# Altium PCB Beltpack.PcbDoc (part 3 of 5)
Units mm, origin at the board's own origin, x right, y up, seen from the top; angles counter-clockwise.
Board outline 85 x 81 mm, 4 copper layers (Top Layer, Inner-1, Inner_GND, Bottom Layer), stack 1.556 mm thick; 389 components, 291 nets, 1372 pads, 660 vias.
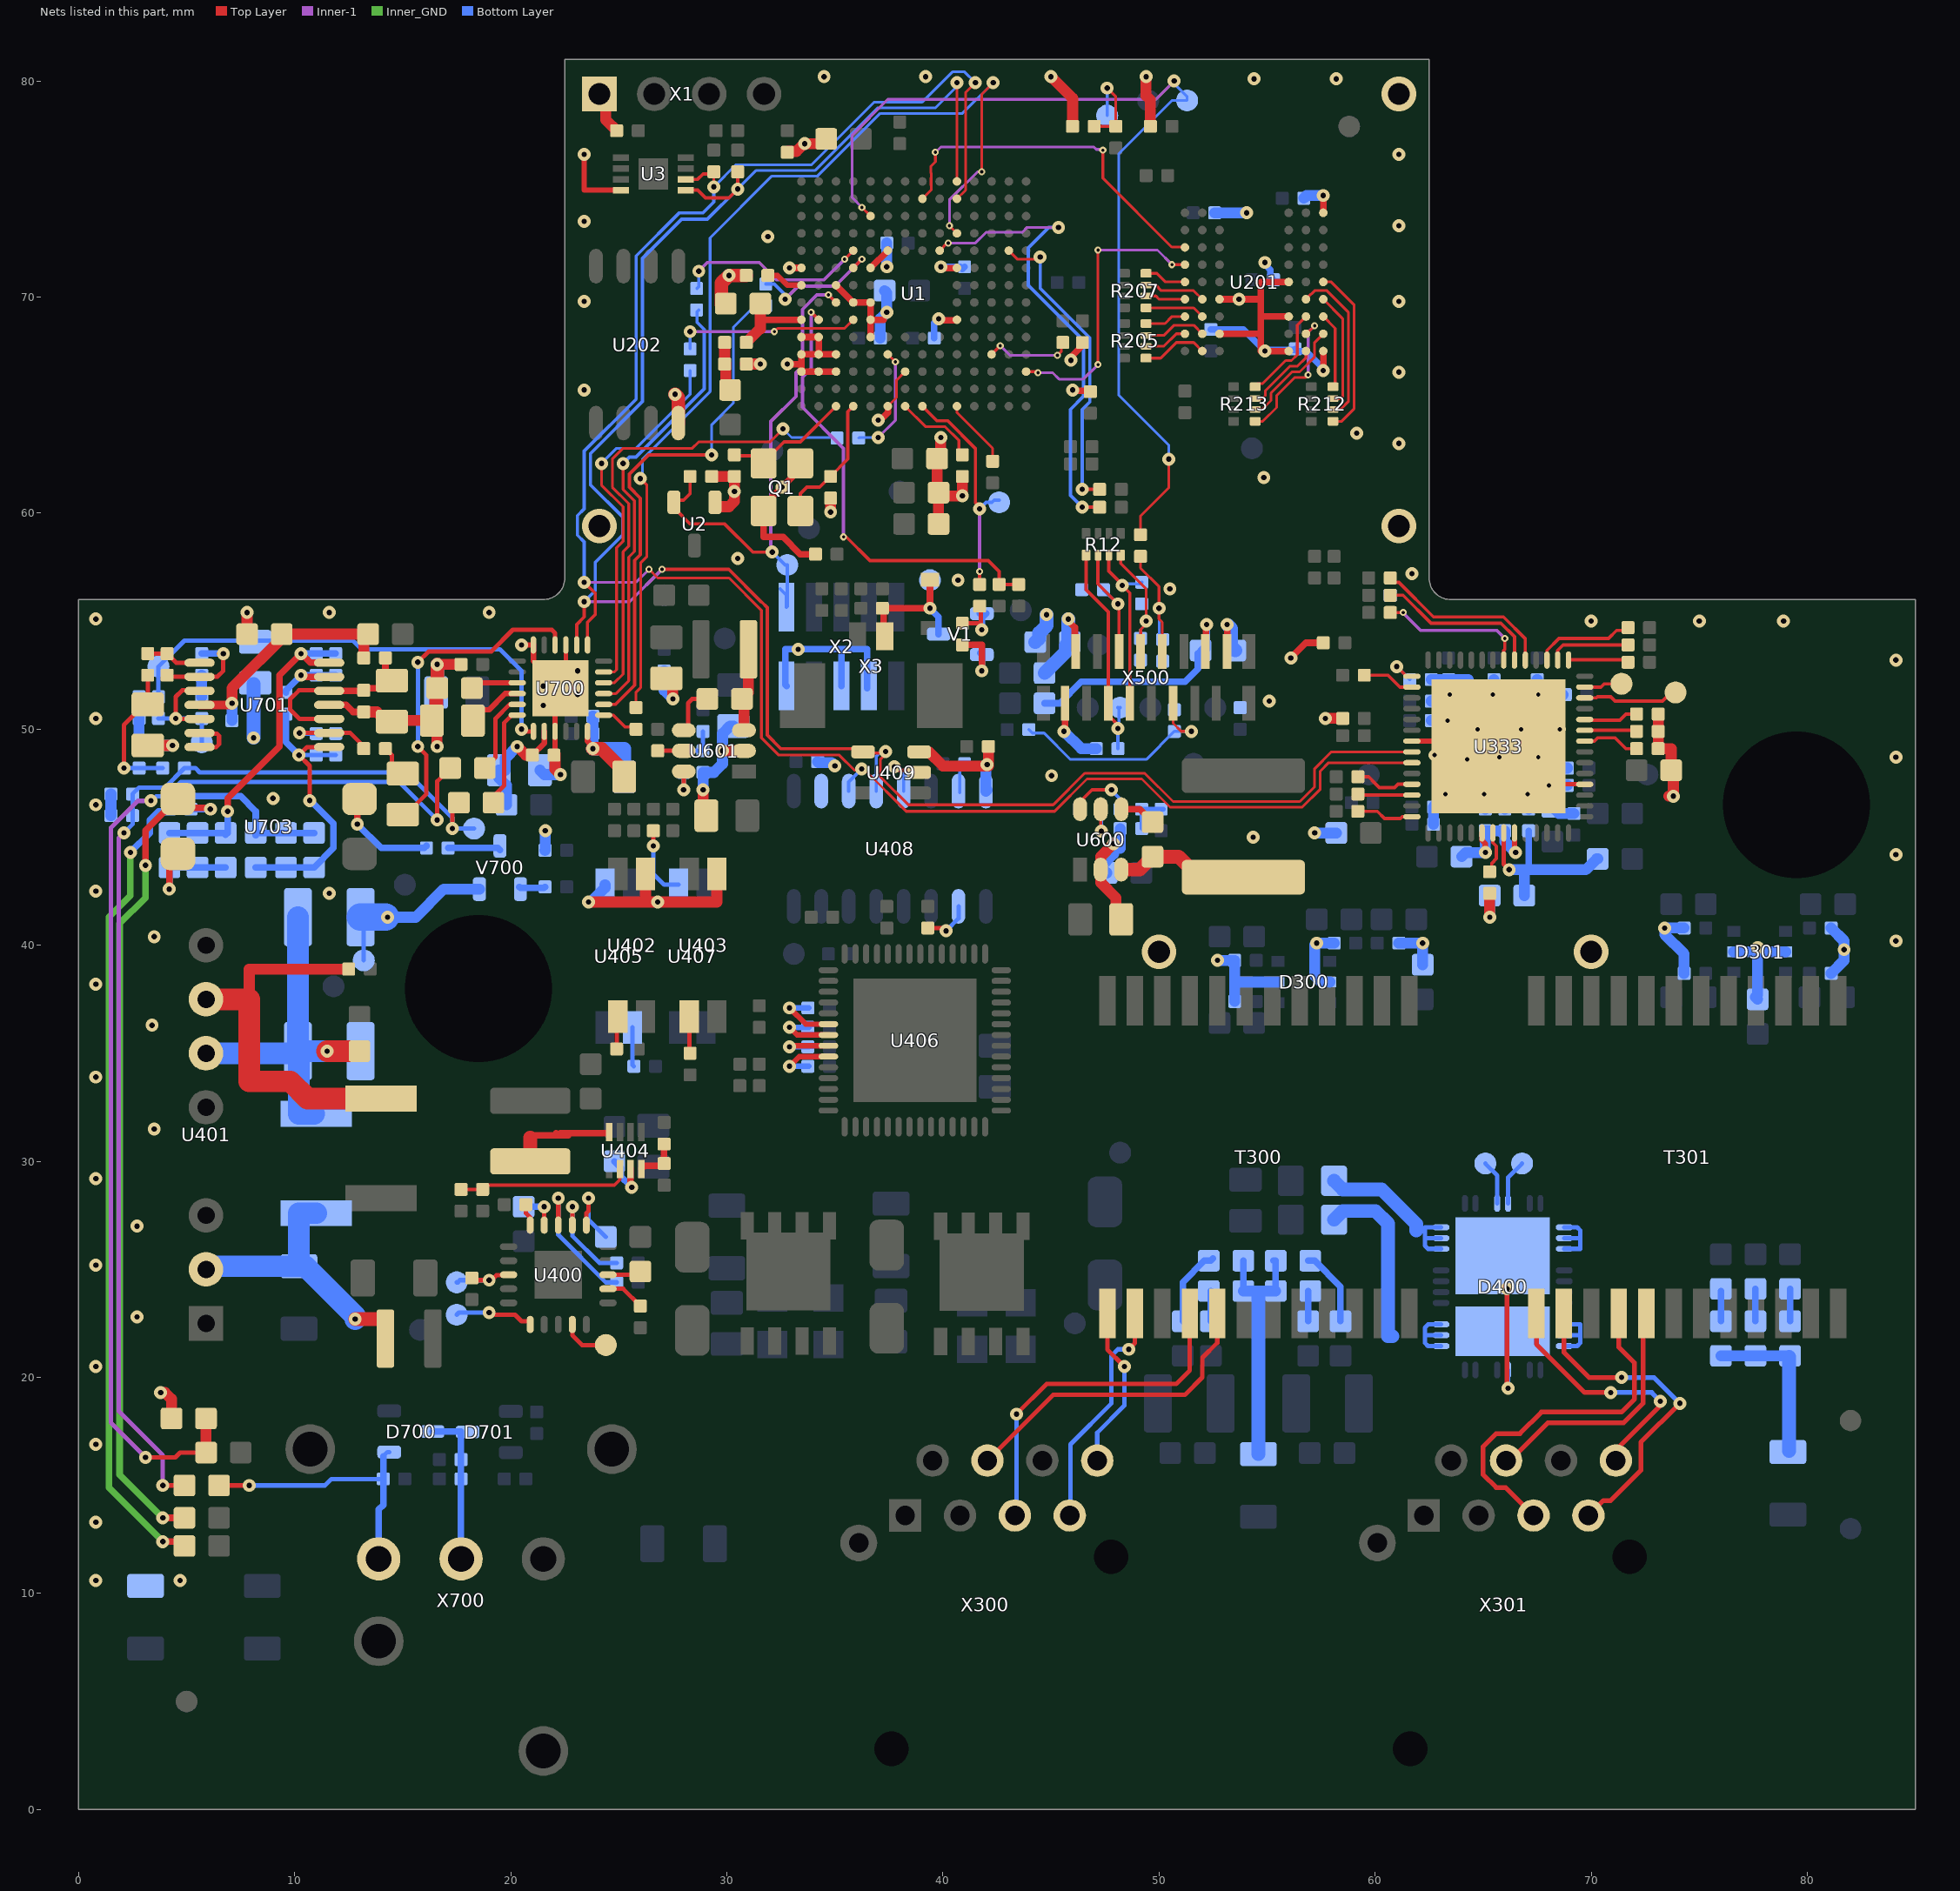
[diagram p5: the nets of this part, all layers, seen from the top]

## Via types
v1: diameter 0.6, hole 0.25, Top Layer to Bottom Layer, 460 vias
v2: diameter 0.325, hole 0.15, Top Layer to Inner-1, 145 vias
v3: diameter 0.55, hole 0.2, Top Layer to Bottom Layer, 41 vias
v4: diameter 0.325, hole 0.15, Top Layer to Inner-1, tented both sides, 8 vias
v5: diameter 1.6, hole 1.016, Top Layer to Bottom Layer, 5 vias
v6: diameter 0.6, hole 0.25, Top Layer to Bottom Layer, tented both sides, 1 vias

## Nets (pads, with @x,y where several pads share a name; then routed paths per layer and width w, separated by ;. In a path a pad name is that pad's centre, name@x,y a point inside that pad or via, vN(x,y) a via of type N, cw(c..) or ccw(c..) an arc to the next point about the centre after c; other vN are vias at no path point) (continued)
GND: C1.2 C2.2 C3.1 C5.1 C6.2 C7.2 C8.2 C9.2 C10.2 C11.2 C12.2 C13.2 C14.2 C15.2 C16.2 C17.1 C18.1 C19.1 C20.1 C21.1 C22.1 C23.1 C24.1 C200.2 C201.2 C202.2 C203.2 C204.2 C205.2 C206.1 C300.2 C301.2 C302.2 C303.2 C304.2 C305.2 C306.2 C307.2 C308.2 C309.2 C310.1 C311.2 C312.2 C313.2 C315.2 C316.2 C317.2 C318.2 C319.2 C320.2 C323.2 C328.2 C330.1 C332.1 C333.2 C334.2 C335.2 C336.2 C406.2 C408.2 C417.1 C418.2 C419.2 C601.2 C602.2 C604.2 C605.1 C606.1 C607.2 C700.1 C701.1 C702.1 C703.1 C704.1 C705.1 C706.1 C707.1 C708.1 C709.1 C713.1 C715.1 C716.2 C717.2 C722.1 C723.1 C724.1 C725.1 C726.1 D300.2 D300.5 D301.2 D301.5 Q1.2 Q1.4 R2.1 R3.2 R9.2 R11.2 R204.2 R208.2 R209.1 R210.2 R218.2 R300.1 R320.2 R321.1 R322.2 R325.1 R331.2 R337.1 R338.1 R603.2 R607.2 R705.2 R707.2 R712.1 R722.2 R723.2 R724.2 TP407.1 U1.A3 U1.A4 U1.A5 U1.A9 U1.B3 U1.B4 U1.B5 U1.C3 U1.C4 U1.C8 U1.D7 U1.E5 U1.E6 U1.E7 U1.E9 U1.F1 U1.F10 U1.G3 U1.K6 U1.K9 U2.1 U3.4 U201.A1 U201.A3 U201.B7 U201.C3 U201.D7 U201.E3 U201.J1 U202.4 U333.4 U333.35 U333.57 U401.7 U402.3 U403.3 U405.3 U408.2 U408.8 U409.3 U600.2 U601.2 U700.3 U700.6 U700.15 U700.18 U700.25 U701.11 V1.2 V700.2 X1.1 X2.3 X2.5 X2.9 X4.1 X5.1 X6.1 X7.1 X8.1 X500.1 X500.16 | length 254.9
  Top Layer w0.127: U1.F1@37.45,64.95 37.85,65.35 37.85,66.15 U1.G3@38.25,66.55
  Top Layer w0.203: U700.25@22.3,51.9 22.55,52.15 U700.15@22.55,53.9 ; U333.57@68,47.4 68.05,47.45 U333.4@69.7,47.45
  Top Layer w0.254: v1(20.5,53.9) U700.18@21.05,53.9 21.05,53.15 U700.25@22.3,51.9 22.05,51.65 U700.3@22.05,49.9 C704.1@22.05,48.85 ; v1(23.4,76.6) 23.4,74.95 U3.4@25.1,74.95 ; U700.6@23.55,49.9 23.55,49.45 23.8,49.2 v1(23.8,49.1) ; U333.35@61.7,49.45 U333.57@65.45,49.45
  Top Layer w0.305: U701.11@11.6,51.125 12.375,51.125 12.7,50.8 R722.2@13.2,50.8 ; Q1.2@31.575,60.225 v1(32.55,61.2) 33.4,62.05 Q1.4@33.4,62.3 ; Q1.2@31.7,60.1 31.7,58.9 32.6,58.9 33.4,58.1 34,58.1 R9.2@34.1,58.2 ; v6(32.9,71.35) U1.A9@33.45,71.35 ; v1@32.95,66.95 33,66.9 33.45,66.9 U1.A3@33.45,66.55 U1.B3@34.25,66.55 U1.C3@35.05,66.55 ; 33.45,66.95 U1.A4@33.45,67.35 U1.B4@34.25,67.35 ; U1.A5@33.45,68.15 U1.B5@34.25,68.15 ; U1.B5@34.25,68.1 U1.B4@34.25,67.35 ; U1.C4@34.95,67.35 U1.B4@34.25,67.35 ; U1.C8@35.05,70.55 U1.D7@35.85,69.75 U1.E7@36.65,69.75 U1.E6@36.65,68.95 ; U1.E5@36.65,68.15 U1.E6@36.65,68.95 ; U1.E9@36.65,71.35 U1.F10@37.45,72.15 U1.F10@37.45,72.2 ; v1(37,64.3) 37.056,64.356 37.156,64.356 37.45,64.65 U1.F1@37.45,64.95 ; 37.25,68.95 U1.E6@36.65,68.95 ; v1(39.8,69) 39.868,68.932 40.632,68.932 U1.K6@40.65,68.95 U1.K6@40.632,68.968 ; v1(39.9,71.4) 39.956,71.344 40.056,71.344 40.068,71.332 40.632,71.332 U1.K9@40.65,71.35 ; R11.2@40.9,53.9 41.8,53.9 v1(41.8,52.7) ; v1@45.65,49.95 X500.1@45.65,51.2 ; v1@45.975,67.125 45.975,67.275 46.45,67.75 46.45,67.894 C206.1@46.456,67.899 ; v1(46,65.7) 46.038,65.663 46.787,65.663 R204.2@46.825,65.625 ; U201.B7@52.8,68.3 54.7,68.3 ; U201.D7@52.8,69.9 54.7,69.9 ; X500.16@53.15,53.6 v1(53.15,54.85) ; U201.A3@56,67.5 54.7,67.5 54.7,68.3 ; U201.C3@56,69.1 54.7,69.1 ; U201.E3@56,70.7 54.7,70.7 54.7,69.9 ; v1(56.1,53.3) 56.8,54 R338.1@57.6,54 ; v1(57.6,66.6) U201.A1@57.6,67.5 ; U201.J1@57.6,73.9 v1(57.6,74.7) ; 54.7,68.3 54.7,69.1 ; 54.7,69.1 54.7,69.9
  Top Layer w0.508: C717.2@3.2,49.25 v1(4.35,49.25) ; v1(3.8,19.3) 4,19.3 4.3,19 R712.1@4.3,18.1 ; C722.1@7.7,54.3 C722.1@7.8,54.4 v1(7.8,55.4) ; 7.9,37.5 7.9,38.9 11.6,38.9 C418.2@12.5,38.9 ; R722.2@13.2,50.8 13.8,50.8 14.1,50.5 C724.1@14.3,50.5 ; C724.1@14.4,50.4 16.085,50.4 16.085,50.489 16.174,50.4 16.3,50.4 C716.2@16.375,50.475 ; C716.2@16.35,50.5 C716.2@16.375,50.475 ; C716.2@16.4,50.5 C716.2@16.375,50.475 ; v1(16.6,49.2) 16.582,49.218 16.582,50.268 16.4,50.45 C716.2@16.375,50.475 ; v1(16.6,53) C700.1@17.7,53 ; C704.1@22.05,48.85 22.05,48.15 v1(22.3,47.9) ; v1(23.6,42) 26.235,42 ; X1.1@24.1,79.4 24.4,79.1 24.4,78.2 C205.2@24.9,77.7 ; U402.3@26.235,43.3 26.235,42 ; C606.1@27.2,52.35 27.5,52.05 v1(27.5,51.4) ; v1(28.9,47.2) 28.9,46.15 C604.2@29.05,46 ; C3.1@29.3,61.7 30.3,61.7 30.35,61.65 v1(30.35,61) 30.35,60.55 30.1,60.3 U2.1@29.45,60.3 ; U403.3@29.535,43.3 29.535,42 v1(26.8,42) 26.235,42 ; v1(29.8,49) U601.2@30.797,49 ; C15.2@30.85,66.9 C15.2@30.9,66.9 v1(31.55,66.9) ; C15.2@30.875,66.875 C15.2@30.9,66.85 ; R209.1@32.8,76.7 32.846,76.746 33.221,76.746 33.575,77.1 v1(33.6,77.1) 34.354,77.1 34.55,77.296 C8.2@34.55,77.5 ; v1(34.8,60.05) C2.2@34.8,60.7 ; U409.3@38.9,48.95 39.35,48.95 40,48.3 42.1,48.3 R210.2@42.1,49.2 ; C6.2@39.7,62.525 39.9,62.725 v1(39.9,63.5) ; C6.2@39.725,62.525 39.725,61.175 39.95,60.95 C11.2@39.9,60.9 ; C14.2@39.8,59.5 C11.2@39.8,60.95 39.85,60.9 C11.2@39.9,60.9 ; R2.1@40.9,61.7 v1(40.9,60.8) 40,60.8 C11.2@39.9,60.9 ; v1(45,80.2) 46,79.2 R218.2@46,77.9 ; v1(47.9,44.7) 47.3,44.1 U600.2@47.3,43.503 47.3,42.9 48,42.2 48,41.492 C601.2@47.954,41.446 ; v1(49.4,80.2) 49.4,79.323 49.6,79.123 R208.2@49.6,77.9 ; v1(57.7,50.5) R337.1@58.5,50.5 ; v1(65.3,41.3) R300.1@65.3,42.4 ; R322.2@73.1,50.7 R320.2@73.1,49.9 R321.1@73.1,49.1 73.7,49.1 C307.2@73.7,48.1 73.6,48 73.8,47.8 v1(73.8,46.9) v1@73.6,46.9
  Top Layer w0.635: C716.2@16.55,50.5 C715.1@16.55,51.9 ; C715.1@16.6,51.9 v1(16.6,53) ; v1(23.8,49.1) 24.2,49.1 25.25,48.05 C703.1@25.25,47.8 ; v1(27.6,65.5) 27.755,65.345 U202.4@27.755,64.168 ; C16.2@29.75,69.65 29.75,70.65 v1(30.1,71) ; v1@30.15,71 R3.2@30.9,71
  Top Layer w1: U401.7@5.9,37.5 7.9,37.5 ; 7.9,37.4 7.9,33.7 9.8,33.7 10.6,32.9 C406.2@14,32.9
  Bottom Layer w0.203: TP407.1@13.2,39.3 C408.2@13.2,40.9
  Bottom Layer w0.305: X2.9@32.76,52 32.7,52.06 32.7,53.7 v1(33.3,53.7) 36.5,53.7 X2.3@36.5,51.9 ; X2.5@35.3,52 35.3,53.6 ; C7.2@39.6,68.1 v1@39.6,68.8 ; v1(39.9,71.4) 40.8,71.4 40.9,71.3 C9.2@41,71.4 ; V1.2@41.725,53.525 V1.2@41.8,53.45 v1(41.8,52.7) ; C204.2@52.4,68.5 53.9,68.5 v1(54.9,67.5) 54.95,67.55 56.25,67.55 C203.2@56.3,67.6 56.4,67.5 56.8,67.5 57.6,66.7 v1(57.6,66.6) ; v1(54.9,71.6) 54.9,71.52 55.152,71.268 55.152,70.948 C202.2@55.3,70.8
  Bottom Layer w0.508: R707.2@1.5,46 C713.1@1.5,47 ; R705.2@2.8,50.5 2.8,49.1 3.7,49.1 ; 3.8,49.2 3.7,49.1 ; v1(4.35,49.25) 3.85,49.25 3.7,49.1 ; C708.1@5.7,51.5 R724.2@5.7,52.5 ; v1(14.3,41.3) 15.6,41.3 16.9,42.6 V700.2@18.55,42.6 ; C705.1@21.35,48.1 21.55,47.9 v1(22.3,47.9) ; R723.2@21.587,44.4 21.594,44.406 21.594,45.294 v1(21.6,45.3) ; v1(23.6,42) 23.7,42 24.365,42.665 U405.3@24.365,42.8 ; v1(23.8,49.1) C706.1@23.8,49.8 C702.1@23.8,50.6 ; 25.25,49.1 25.3,49.1 ; C605.1@27.1,52.7 27.1,51.8 v1(27.5,51.4) ; v1(28.9,47.2) R607.2@28.9,48 29.4,48 29.8,48.4 v1(29.8,49) 29.8,49.8 30.15,50.15 C607.2@30.3,50.15 ; C417.1@34.2,48.5 34.246,48.454 34.846,48.454 v1(35,48.3) ; C10.2@37.1,68.1 37.1,69 v1(37.4,69.3) 37.4,70.2 C13.2@37.3,70.3 ; v1(37.4,71.4) C12.2@37.4,72.5 ; U408.8@42.045,47.189 U408.8@41.99,47.134 41.99,48.312 v1(42.045,48.367) ; v1(45.6,49.9) 46.4,49.1 C24.1@47.1,49.1 ; C602.2@47.58,43.351 47.3,43.63 47.9,44.23 v1(47.9,44.7) 48,44.7 48.2,44.5 R603.2@48.2,45.4 ; C200.2@52.575,73.9 v1(54.05,73.9) ; v1(52.7,39.3) C328.2@53.5,39.3 53.5,38.3 ; C323.2@53.5,37.4 53.5,38.3 ; D300.5@55.5,38.3 53.5,38.3 ; C201.2@56.7,74.575 56.825,74.7 v1(57.6,74.7) ; v1(57.2,45.2) C317.2@58.2,45.2 ; D300.2@57.9,38.3 57.898,38.302 57.498,38.302 57.211,38.589 57.211,40.011 v1(57.3,40.1) C319.2@58.1,40.1 ; C320.2@61.1,40.1 v1(62.2,40.1) C330.1@62.2,39.1 ; C310.1@62.6,50.4 v3(63.35,50.4) 63.4,50.4 v3@63.4,51.4 ; C305.2@62.6,51.3 63.3,51.3 v3@63.4,51.4 ; R325.1@62.6,52.3 C304.2@63.4,52.3 ; C318.2@62.7,45.6 C306.2@62.7,46.4 v3@63.2,46.9 ; 64.3,52.3 C304.2@63.4,52.3 ; C315.2@65.1,46.3 65.1,47.1 66,47.1 ; v1(65.3,41.3) C311.2@65.3,42.3 ; C309.2@65.5,52.3 65.5,51.6 v3@67.5,51.6 ; C316.2@66,46.3 66,47.1 ; C300.2@67.1,46.3 67.1,47.1 66,47.1 ; C303.2@67.5,52.3 v3@67.5,51.6 ; v3@68.2,47.4 C301.2@68.9,47.4 ; C302.2@68.7,51.6 v3(67.55,51.6) v3@67.5,51.6 ; C308.2@68.9,48.2 68,48.2 68,46.6 C312.2@68.2,46.4 68.5,46.1 C313.2@69.2,46.1 ; C333.2@74.3,38.7 74.3,39.6 73.4,40.5 v1(73.4,40.8) C334.2@74.3,40.8 ; D301.2@76.6,39.7 77.5,39.7 v1(77.7,39.9) ; C332.1@77.7,37.5 77.6,37.6 77.7,37.7 v1(77.7,39.9) ; D301.5@79,39.7 77.9,39.7 v1(77.7,39.9) ; C336.2@81.1,38.7 81.7,39.3 v1(81.7,39.8) 81.7,40.2 C335.2@81.1,40.8 ; v3@63.4,51.4 C304.2@63.4,52.3
  Bottom Layer w0.635: v1(8.1,49.6) C726.1@8.1,52.1 ; C701.1@16.55,51.7 16.6,51.75 v1(16.6,53) ; v1(23.8,49.1) 25.25,49.1 C707.1@25.25,47.8 ; C18.1@44.275,54.032 44.457,54.215 44.457,54.457 44.8,54.8 v1(44.8,55.3) ; v1@53.2,54.8 53.343,54.657 53.343,53.825 C17.1@53.525,53.643
  Bottom Layer w1.27: C408.2@13.05,41.3 v1@14.2,41.3
  other v1: 0.8,10.6 4.7,10.6 0.8,13.3 0.8,16.9 0.8,20.5 2.7,22.8 0.8,25.2 2.7,27 0.8,29.2 3.5,31.5 0.8,33.9 3.4,36.3 0.8,38.2 84.1,40.2 3.5,40.4 11.6,42.4 0.8,42.5 84.1,44.2 54.35,45 0.8,46.5 9,46.8 45.025,47.85 84.1,48.7 0.8,50.5 21.5,51.1 55.1,51.3 23.1,51.6 21.5,52 23.1,52.7 84.1,53.2 70,55 75,55 78.9,55 0.8,55.1 11.6,55.4 19,55.4 50.5,56.5 40.7,56.9 61.7,57.2 30.5,57.9 54.85,61.65 61.1,63.225 59.15,63.7 23.4,65.7 61.1,66.525 32.8,66.9 45.925,67.075 23.4,69.8 61.1,69.8 53.7,69.9 31.9,72.8 61.1,73.3 23.4,73.5 61.1,76.6 54.4,80.1 58.2,80.1 34.5,80.2 39.2,80.2
  other v3: 63.25,47 65.05,47 67.05,47 68.05,47.4 64.25,48.6 65.75,48.7 67.55,48.7 62.75,48.8 64.75,50 66.75,50 68.55,50 63.45,51.6 65.45,51.6
  other v5: 50,39.7 70,39.7 24.1,59.4 61.1,59.4 61.1,79.4
HP_BIAS: C724.2 R720.2 R722.1 U701.10 U701.12 | length 8.3
  Top Layer w0.203: U701.10@11.6,50.475 10.225,50.475 9.8,50.9 9.8,51.4 10.2,51.8 U701.12@11.6,51.8
  Top Layer w0.305: U701.12@11.6,51.775 R722.1@13.025,51.775 ; R722.1@13.2,51.8 13.3,51.9 14.2,51.9 C724.2@14.5,52.2 ; C724.2@14.2,52.3 R720.2@14.2,53.3
I2C0_SCL: R15.2 U1.K13 U3.6 U333.37 U408.3 U700.13 | length 97.6
  Top Layer w0.127: v2(26.4,57.4) 26.8,57 30.105,57 31.6,55.505 31.6,49.6 32.4,48.8 35.205,48.8 35.905,48.1 36.4,48.1 38.3,46.2 45.171,46.2 46.669,47.698 49.201,47.698 50.512,46.388 56.622,46.388 57.462,47.228 57.462,48.062 57.85,48.45 U333.37@61.7,48.45 ; v1(29.4,75.1) 29.4,75.2 R15.2@29.4,75.8 ; U1.K13@40.65,74.55 41.05,74.95 41.05,79.475 41.375,79.8 v1@41.55,79.8
  Top Layer w0.152: v1(23.4,56.8) 23.911,56.289 23.911,55.305 23.55,54.944 U700.13@23.55,53.9 ; U3.6@28.1,75.45 28.65,75.45 28.9,75.7 R15.2@29.3,75.7
  Inner-1 w0.127: v1(23.4,56.8) 25.8,56.8 v2(26.4,57.4)
  Bottom Layer w0.127: v1(29.4,75.1) 30.424,76.124 33.924,76.124 36.824,79.024 39.044,79.024 40.444,80.423 41.002,80.423 v1(41.5,79.925)
  Bottom Layer w0.152: v1(23.4,56.8) 23.4,58.67 23.089,58.981 23.089,59.889 23.4,60.2 23.4,62.877 25.8,65.277 25.8,71.9 27.8,73.9 28.9,73.9 29.4,74.4 v1(29.4,75.1) ; U408.3@35.64,47.134 35.64,47.562 v1(36.245,48.167)
I2C0_SDA: R16.2 U1.K14 U3.5 U333.36 U408.4 U409.4 U700.14 | length 99.3
  Top Layer w0.127: v1@37.4,48.9 37.1,48.6 37.1,47.8 38.4,46.5 45.1,46.5 46.561,47.961 49.339,47.961 50.65,46.65 56.514,46.65 57.2,47.336 57.2,48.171 57.979,48.95 U333.36@61.7,48.95 ; U1.K14@40.65,75.35 40.65,77.8 v1(40.65,79.925)
  Top Layer w0.152: U700.14@23.05,53.9 23.05,54.85 23.4,55.2 v1(23.4,55.9) ; v2(27,57.4) 30.094,57.4 31.597,55.897 ; U3.5@28.1,74.95 28.65,74.95 29.011,74.589 30.089,74.589 v1(30.5,75) R16.2@30.5,75.8 ; 31.6,55.9 31.875,55.625 31.875,49.725 32.5,49.1 35.9,49.1 36.05,48.95 U409.4@36.3,48.95 36.35,49 36.45,48.9 v1@37.4,48.9 ; U1.K14@40.65,75.35 U1.K14@40.661,75.361
  Inner-1 w0.152: v1(23.4,55.9) 25.5,55.9 v2(27,57.4)
  Bottom Layer w0.127: v1(30.5,75) 31.362,75.862 34.091,75.862 36.991,78.762 39.662,78.762 40.65,79.75 v1(40.65,79.925)
  Bottom Layer w0.152: v1(23.4,55.9) 23.911,56.411 23.911,57.721 25.19,59 25.19,59.81 23.689,61.311 23.689,62.759 26.1,65.171 26.1,71.794 27.906,73.6 29.1,73.6 v1(30.5,75) ; U408.4@36.91,47.134 36.91,48.732 37.145,48.967 v1(37.345,48.967)
I2S_LRCK: R215.2 U700.9 | length 20.8
  Top Layer w0.127: U700.9@24.3,51.65 24.871,51.65 25.462,52.241 25.462,57.962 25.724,58.224 25.724,60.576 25.2,61.1 v1(25.2,62.3)
  Bottom Layer w0.152: v1(25.2,62.3) 25.489,62.589 25.789,62.589 28.952,65.752 28.952,68.5 28.624,68.828 28.624,69.324 R215.2@28.7,69.4
I2S_MCLK: R18.2 U700.11 | length 17.3
  Top Layer w0.127: v1(24.2,62.3) 24.2,61.3 25.2,60.3 25.2,58.7 24.9,58.4 24.9,52.75 24.8,52.65 U700.11@24.3,52.65
  Bottom Layer w0.127: v1(24.2,62.3) 24.9,63 25.805,63 28.3,65.495 R18.2@28.3,66.6
I2S_SCLK: R217.2 U700.10 | length 22.4
  Top Layer w0.127: U700.10@24.3,52.15 24.8,52.15 25.2,52.55 25.2,58.211 25.462,58.473 25.462,60.438 24.7,61.2 24.7,62.505 25.195,63 28.4,63 28.7,63.3 32,63.3 v1(32.6,63.9)
  Bottom Layer w0.127: v1(32.6,63.9) 33,63.5 R217.2@34.9,63.5
I2S_SDIN: R702.2 U1.K11 | length 47.6
  Top Layer w0.127: R702.2@25.8,51 25.8,51.712 26.011,51.923 26.011,57.7 26.3,57.989 26.3,61.3 v1(26,61.6) ; v2(40.3,73.3) U1.K11@40.65,72.95 ; v2(41.8,75.8) 41.8,79.4 42.2,79.8 v1@42.4,79.8
  Inner-1 w0.127: v2(40.3,73.3) 40.3,74.5 41.6,75.8 v2(41.8,75.8)
  Bottom Layer w0.127: v1(26,61.6) 26.091,61.691 26.091,62.49 29.227,65.627 29.227,72.738 32.089,75.6 32.6,75.6 34.2,75.6 37.1,78.5 40.9,78.5 v1(42.325,79.925)
I2S_SDOUT: R216.2 U700.8 | length 24.4
  Top Layer w0.152: U700.8@24.3,51.15 24.85,51.15 25.737,52.037 25.737,57.814 26,58.077 26,60.688 25.489,61.2 25.489,61.812 26.377,62.7 v1(29.3,62.7)
  Bottom Layer w0.127: v1(29.3,62.7) 29.3,64.1 30.3,65.1 30.3,68.6 31.3,69.6 R216.2@31.8,69.6 R216.2@31.9,69.6
LCD_A0: R14.1 TP8.1 U1.E12 | length 44.5
  Top Layer w0.127: v2(36.25,74.15) U1.E12@36.65,73.75 ; R14.1@49.141,59 49.141,59.866 50.45,61.175 v1(50.45,62.5)
  Inner-1 w0.127: v2(36.25,74.15) 35.8,74.6 35.8,77.5 37.45,79.15 49.85,79.15 v1(50.7,80)
  Bottom Layer w0.127: v1(50.45,62.5) 50.45,63.15 48.137,65.463 48.137,76.637 50.6,79.1 TP8.1@51.3,79.1 51.3,79.272 50.7,79.872 v1(50.7,80)
MOTOR_ON: R10.1 TP14.1 U1.H1 | length 10.7
  Top Layer w0.152: U1.H1@39.05,64.95 39.727,64.273 40.22,64.273 41.5,62.993 41.5,60.5 41.7,60.3 v1(41.7,60.2) ; R10.1@41.7,56.7 v2(41.7,57.3)
  Inner-1 w0.152: v2(41.7,57.3) v1(41.7,60.2)
  Bottom Layer w0.152: v1(41.7,60.2) 42,60.5 42.266,60.5 42.366,60.6 TP14.1@42.6,60.6
NCS0: U1.H13 U201.G9 | length 16.8
  Top Layer w0.127: U1.H13@39.05,74.55 39.459,74.96 39.459,75.177 39.451,75.185 39.451,75.515 39.459,75.523 39.459,75.73 39.439,75.75 39.439,76.049 39.65,76.26 v2(39.65,76.7) ; v2(47.4,76.8) 47.4,75.504 50.586,72.318 51.182,72.318 U201.G9@51.2,72.3
  Inner-1 w0.127: v2(39.65,76.7) 39.656,76.7 39.902,76.947 46.986,76.947 47.095,76.838 47.362,76.838 v2(47.4,76.8)
NetC1_1: C1.1 Q1.1 U1.C1 | length 6
  Top Layer w0.152: C1.1@30.35,62.65 31.35,62.65 Q1.1@31.675,62.325 ; Q1.1@31.65,62.3 Q1.1@31.675,62.325 ; Q1.1@31.7,62.3 Q1.1@31.675,62.325 ; U1.C1@35.05,64.95 35,64.9 33.4,63.3 32.65,63.3 Q1.1@31.675,62.325
NetC2_1: C2.1 Q1.3 U1.D1 | length 6.4
  Top Layer w0.152: Q1.3@33.4,60.1 33.4,60.9 33.7,61.2 34.3,61.2 C2.1@34.8,61.7 ; C2.1@34.825,61.675 34.8,61.65 34.75,61.65 C2.1@34.8,61.7 ; U1.D1@35.85,64.95 35.6,64.7 35.6,62.5 C2.1@34.8,61.7
NetC4_2: C4.2 D1.A TP13.1 V1.3 X3.2 | length 7.5
  Top Layer w0.305: X3.2@37.3,54.3 37.25,54.35 37.25,55.55 C4.2@37.2,55.6 v1(39.4,55.6) D1.A@39.4,56.9
  Bottom Layer w0.305: TP13.1@39.4,56.9 v1(39.4,55.6) 39.8,55.2 V1.3@39.8,54.4
NetC15_1: C15.1 L1.1 R19.1 | length 2.3
  Top Layer w0.508: C15.1@29.9,66.9 R19.1@29.9,67.9 ; L1.1@29.95,65.6 C15.1@29.95,66.9
NetC16_1: C16.1 R19.2 U1.A6 | length 4
  Top Layer w0.305: 31.55,68.95 U1.A6@33.45,68.95
  Top Layer w0.508: R19.2@30.9,67.9 31.525,68.526 31.55,68.526 31.55,68.95 C16.1@31.55,69.45 ; C16.1@31.5,69.4 C16.1@31.7,69.6
NetC17_2: C17.2 L2.1 X500.14 | length 11.2
  Top Layer w0.305: X500.14@52.15,53.6 52.175,53.625 52.175,54.825 v1(52.2,54.85)
  Bottom Layer w0.305: L2.1@44.7,51.2 45.4,51.2 46.4,52.2 51.2,52.2 51.8,52.8 51.8,53.5 C17.2@52,53.7 ; v1(52.2,54.85) 52.15,54.85 52.213,54.787 52.213,54.056 52.225,54.043 C17.2@52.225,53.7
NetC18_2: C18.2 L3.1 X500.2 | length 4.7
  Top Layer w0.305: v1(45.8,55.1) 45.8,55.02 46.102,54.718 46.102,53.648 X500.2@46.15,53.6
  Bottom Layer w0.635: L3.1@44.7,52.6 45.692,53.592 45.692,53.892 C18.2@45.853,54.053 ; v1(45.8,55.1) 45.8,54.107 C18.2@45.853,54.053 ; C18.2@45.875,54.032 C18.2@45.853,54.053
NetC19_2: C19.2 R17.2 X500.11 | length 10.6
  Top Layer w0.127: X500.11@50.65,51.2 50.65,50.275 51.025,49.9 v1(51.5,49.9)
  Bottom Layer w0.127: R17.2@43.975,49.983 44.136,49.822 44.678,49.822 45.9,48.6 49.408,48.6 C19.2@50.708,49.9 v1(51.5,49.9)
NetC20_2: C20.2 R12.8 X500.8 | length 6
  Top Layer w0.127: R12.8@48.225,58.059 48.225,57.675 49.4,56.5 v1(49.4,55) 49.4,54.872 49.15,54.622 X500.8@49.15,53.6
  Bottom Layer w0.127: C20.2@49.142,54.2 49.15,54.207 49.15,54.622 49.4,54.872 v1(49.4,55)
NetC21_2: C21.2 R12.6 X500.6 | length 5.8
  Top Layer w0.152: R12.6@47.175,58.059 47.175,56.725 v1(48.1,55.8) 48.15,55.75 X500.6@48.15,53.6
  Bottom Layer w0.152: C21.2@47.425,56.458 47.709,56.174 47.726,56.174 v1(48.1,55.8)
NetC22_2: C22.2 R14.2 X500.10 | length 6.5
  Top Layer w0.127: R14.2@49.141,58 49.141,57.459 50,56.6 v1(50,55.6) 50,55.1 50.15,54.95 X500.10@50.15,53.6 ; X500.10@50.2,53.4 X500.10@50.2,53.6
  Bottom Layer w0.127: v1(50,55.6) 50.004,55.596 50.004,54.315 C22.2@50.169,54.15
NetC23_2: C23.2 R12.7 X500.7 | length 8.2
  Top Layer w0.152: R12.7@47.675,58.059 47.675,57.325 48.3,56.7 v1(48.3,56.652) 48.65,56.302 X500.7@48.65,51.2
  Bottom Layer w0.152: v1(48.3,56.652) 48.374,56.726 49.126,56.726 C23.2@49.2,56.8
NetC24_2: C24.2 R12.5 TP3.1 X500.5 | length 10.6
  Top Layer w0.152: R12.5@46.625,58.059 46.625,56.45 47.65,55.425 X500.5@47.65,51.2 47.726,51.124 47.726,50.574 48.1,50.2 v1(48.1,50.035)
  Bottom Layer w0.152: C24.2@48.1,49.1 v1(48.1,50.035) 48.15,50.085 TP3.1@48.15,50.95 ; TP3.1@48.1,51 TP3.1@48.15,50.95 ; TP3.1@48.2,51 TP3.1@48.15,50.95
NetC300_1: C300.1 C311.1 L300.2 U333.50 | length 9.1
  Top Layer w0.203: U333.50@65.95,45.2 65.95,43.75 v1(66.2,43.5)
  Top Layer w0.508: v1(66.2,43.5) v1@66.218,43.482
  Bottom Layer w0.305: 67.1,43.5 C300.1@67.1,45.3
  Bottom Layer w0.508: v1(66.2,43.5) 66.9,43.5 ; C311.1@66.9,42.3 66.9,43.5 ; L300.2@70.3,44 70.25,44 69.75,43.5 67.1,43.5 66.9,43.5
NetC315_1: C315.1 C316.1 L301.2 U333.48 U333.51 | length 6.3
  Top Layer w0.254: U333.48@64.95,45.2 64.95,44.85 65.097,44.703 65.097,44.303 v1(65.1,44.3) ; U333.51@66.45,45.2 66.45,44.35 v1(66.5,44.3)
  Bottom Layer w0.254: C315.1@65,45.3 C315.1@65.1,45.3
  Bottom Layer w0.508: L301.2@64,44.1 64.182,44.282 65.082,44.282 v1(65.1,44.3) C315.1@65.1,45.3 C316.1@66,45.3 66,44.8 v1(66.5,44.3)
NetC321_2: C321.2 R309.2 | length 1.4
  Bottom Layer w0.305: C321.2@56.9,22.6 R309.2@56.9,24
NetC322_2: C322.2 R310.2 | length 3.6
  Bottom Layer w0.305: R310.2@56.9,25.4 R310.2@57,25.4 57.2,25.4 58.4,24.2 C322.2@58.4,22.6
NetC324_2: C324.2 R311.2 | length 1.4
  Bottom Layer w0.305: C324.2@52.4,22.6 R311.2@52.4,24
NetC325_2: C325.2 R312.2 | length 3.7
  Bottom Layer w0.305: C325.2@51.1,22.6 51.1,24.4 52.1,25.4 R312.2@52.3,25.4 52.4,25.4 R312.2@52.5,25.5
NetC326_2: C326.2 R316.2 | length 1.5
  Bottom Layer w0.305: R316.2@79.2,22.6 C326.2@79.2,24.1
NetC327_2: C327.2 R317.2 | length 1.4
  Bottom Layer w0.305: R317.2@76,22.6 C327.2@76,24
NetC329_2: C329.2 R318.2 | length 1.5
  Bottom Layer w0.305: R318.2@77.6,22.6 C329.2@77.6,24.1
NetC331_1: C331.1 R309.1 R310.1 R311.1 R312.1 | length 11.7
  Bottom Layer w0.305: R311.1@53.9,24 R312.1@53.9,25.4 ; R309.1@55.4,24 R310.1@55.4,25.4
  Bottom Layer w0.508: R311.1@53.9,24 R309.1@55.4,24
  Bottom Layer w0.635: C331.1@54.6,16.448 54.6,23.8
NetC337_1: C337.1 R316.1 R317.1 R318.1 | length 7.7
  Bottom Layer w0.508: R317.1@76,21 R318.1@77.6,21 R316.1@79.2,21 R316.1@79.15,20.95 ; C337.1@79.1,16.548 C337.1@79.15,16.598
  Bottom Layer w0.635: C337.1@79.15,16.598 R316.1@79.15,20.95
NetC400_1: C400.1 C407.1 L400.2 U401.2 | length 13
  Top Layer w0.635: v1(12.8,22.7) L400.2@14.2,22.7 ; L400.2@14.2,21.5 L400.2@14.2,21.8
  Bottom Layer w1: U401.2@5.9,25 6.048,25.148 C407.1@10.2,25.148 ; C400.1@11,27.6 10.2,27.6 C407.1@10.2,25.148 ; v1(12.8,22.7) 12.8,22.84 10.492,25.148 C407.1@10.2,25.148
NetC400_2: C400.2 C408.1 C419.1 L404.2 U401.6 | length 16.9
  Top Layer w1: v1(11.5,35.1) L404.2@12.8,35.1
  Bottom Layer w1: U401.6@5.9,35 C419.1@10.146,35 ; C419.1@10.1,34.9 10.15,34.95 C419.1@10.15,35.05 ; C419.1@10.146,35.4 C419.1@10.15,35.4 ; C408.1@10.15,41.3 C419.1@10.15,35.4 ; C400.2@10.9,32.2 10.2,32.2 C419.1@10.2,35.1 ; v1(11.5,35.1) C419.1@10.2,35.1 ; C419.1@10.15,35.05 C419.1@10.2,35.1 ; C419.1@10.15,35.05 C419.1@10.15,35.1 C419.1@10.15,35.4
NetC403_1: C403.1 D400.1 D400.2 D400.3 D400.30 D400.31 D400.32 D400.41 L401.1 | length 14.6
  Bottom Layer w0.203: D400.1@63.05,21.45 62.45,21.45 62.3,21.6 62.3,21.9 ; D400.2@63.05,21.95 62.35,21.95 62.3,21.9 ; D400.3@63.05,22.45 62.45,22.45 62.3,22.3 62.3,21.9 ; D400.32@68.75,21.45 69.35,21.45 69.5,21.6 69.5,21.9 ; D400.31@68.75,21.95 69.45,21.95 69.5,21.9 ; D400.30@68.75,22.45 69.5,22.45 69.5,21.9
  Bottom Layer w0.635: L401.1@58.1,27.3 58.5,27.7 C403.1@59.7,27.7 60.014,27.7 60.6,27.114 60.6,21.9 60.8,21.9
NetC403_2: C403.2 D400.10 D400.11 D400.12 D400.21 D400.22 D400.23 D400.36 D400.42 L402.1 | length 17
  Top Layer w0.203: v1(66.1,24.1) 66.1,19.55 v1(66.15,19.5)
  Bottom Layer w0.203: D400.10@63.05,25.95 62.45,25.95 62.3,26.1 62.3,26.4 ; D400.11@63.05,26.45 62.35,26.45 62.3,26.4 ; D400.12@63.05,26.95 62.3,26.95 62.3,26.4 ; v1(66.1,24.1) D400.42@66.1,24.3 ; v1(66.15,19.5) D400.36@66.15,20.345 ; D400.23@68.75,25.95 69.5,25.95 69.5,26.4 ; D400.22@68.75,26.45 69.45,26.45 69.5,26.4 ; D400.21@68.75,26.95 69.35,26.95 69.5,26.8 69.5,26.4
  Bottom Layer w0.635: L402.1@58.1,29.1 58.5,28.7 C403.2@59.7,28.7 60.3,28.7 61.9,27.1 61.9,26.8
NetC410_1: C410.1 U404.3 | length 2.3
  Top Layer w0.305: v1@25.55,28.75 U404.3@25.55,29.65
  Bottom Layer w0.305: C410.1@24.8,30 25.1,29.7 25.1,29.3 v1@25.5,28.9
  other v1: 25.6,28.8
NetC600_1: C600.1 U600.4 | length 1.7
  Top Layer w0.305: U600.4@48.253,46.297 49.103,46.297 C600.1@49.7,45.7
NetC600_2: C600.2 L600.1 U600.3 | length 6.5
  Top Layer w0.203: U600.3@48.253,43.503 U600.3@48.255,43.5
  Top Layer w0.635: U600.3@48.255,43.5 49.1,43.5 C600.2@49.7,44.1 50.9,44.1 51.9,43.1 53.9,43.1 L600.1@54,43.2
NetC603_1: C603.1 U601.4 | length 2.3
  Top Layer w0.203: U601.4@28.003,49.952 28.2,50.149 28.2,51.2 28.4,51.4 C603.1@29.1,51.4
NetC603_2: C603.2 L602.1 U601.3 | length 4
  Top Layer w0.508: C603.2@30.6,51.4 C603.2@30.65,51.45 ; U601.3@30.797,49.952 30.797,51.303 C603.2@30.7,51.4 31,51.7 L602.1@31,53.7
NetC704_2: C704.2 C705.2 L700.1 U700.2 | length 5.3
  Top Layer w0.254: C704.2@21,48.8 21.55,49.35 U700.2@21.55,49.9
  Top Layer w0.508: v1(20.3,49.2) 20.7,48.8 C704.2@21,48.8
  Bottom Layer w0.508: C705.2@19.45,48.1 19.45,47.75 19.8,47.4 L700.1@19.8,46.5 ; C705.2@19.75,48.1 19.75,48.65 v1(20.3,49.2)
NetC708_2: C708.2 R700.1 TP701.1 U701.3 U701.5 | length 6.3
  Top Layer w0.203: v1(4.5,50.5) 4.5,51.5 4.8,51.8 U701.3@5.6,51.8 ; v1@4.6,50.475 U701.5@5.6,50.475
  Bottom Layer w0.203: R700.1@3.7,50.5 v1(4.5,50.5) C708.2@5.7,50.5 TP701.1@5.7,49.4
NetC710_1: C710.1 C713.2 L701.2 R706.1 R707.1 TP703.1 | length 53.2
  Top Layer w0.203: v1(3.9,15) L701.2@4.9,15 ; v1(17.3,45.4) 17.3,46.3 C710.1@17.6,46.6
  Inner-1 w0.203: v1(2.1,45.2) 1.863,44.963 1.863,18.437 3.9,16.4 v1(3.9,15)
  Bottom Layer w0.203: v1(2.1,45.2) 2.5,45.6 R707.1@2.5,46 C713.2@2.5,47 2.8,47.3 4,47.3 R706.1@4.9,48.2 5.408,48.2 5.608,48 15.199,48 17.3,45.899 v1(17.3,45.4) TP703.1@18.3,45.4
NetC710_2: C710.2 U700.24 | length 4.8
  Top Layer w0.203: C710.2@18.9,46.6 19.7,47.4 19.7,50.3 20.05,50.65 U700.24@20.3,50.65
NetC711_1: C711.1 D700.3 D701.3 R703.1 X700.G | length 7.1
  Bottom Layer w0.305: D700.3@16.376,17.496 17.7,17.496 C711.1@17.7,16.2 R703.1@17.7,15.3 X700.G@17.7,11.7
NetC712_1: C712.1 U700.16 | length 15.1
  Top Layer w0.203: C712.1@15.2,46.1 16.1,47 16.1,48.8 v1(15.7,49.2) ; v1(15.7,53.1) 16.2,53.6 19.1,53.6 20.1,54.6 21.9,54.6 22.05,54.45 U700.16@22.05,53.9
  Bottom Layer w0.203: v1(15.7,49.2) v1(15.7,53.1)
NetC712_2: C712.2 R711.2 | length 1.5
  Top Layer w0.203: R711.2@14.2,49.1 14.5,48.8 14.5,48.4 C712.2@15,47.9
NetC714_1: C714.1 L702.2 R712.2 | length 53.5
  Top Layer w0.203: v1(3.1,16.3) 4.476,16.3 4.699,16.524 L702.2@5.904,16.524 ; v1(16.6,45.8) 16.6,47.587 17.2,48.187 C714.1@17.2,48.2
  Top Layer w0.508: L702.2@5.7,16.72 5.9,16.92 R712.2@5.9,18.1
  Inner-1 w0.203: v1(3.1,16.3) 1.5,17.9 1.5,45.437 2.745,46.682 3.342,46.682 v1(3.35,46.69)
  Bottom Layer w0.203: v1@3.37,46.67 3.6,46.9 4.078,46.9 4.74,47.562 14.838,47.562 v1(16.6,45.8)
NetC714_2: C714.2 U700.23 | length 3.8
  Top Layer w0.203: C714.2@18.8,48.2 19.3,48.7 19.3,50.5 19.95,51.15 U700.23@20.3,51.15
NetC715_2: C715.2 U700.21 | length 2.1
  Top Layer w0.254: C715.2@18.5,51.9 18.5,52.15 U700.21@20.3,52.15
NetC716_1: C716.1 U700.22 | length 2.6
  Top Layer w0.254: C716.1@18.45,50.5 18.45,50.9 19,50.9 19.75,51.65 U700.22@20.3,51.65
NetC717_1: C717.1 C725.2 R701.2 R706.2 | length 6.7
  Top Layer w0.203: v1@2.1,48.1 2.1,50.2 3.05,51.15 C717.1@3.2,51.15 R701.2@3.2,52.5
  Bottom Layer w0.203: v1(2.1,48.2) C725.2@2.8,48.2 R706.2@3.9,48.2
NetC720_1: C720.1 R715.1 R716.2 R717.2 R718.2 U701.14 | length 15.6
  Top Layer w0.305: v1(6.9,46.2) 6.9,46.8 9.3,49.2 9.3,52.5 v1(10.3,53.5) 10.725,53.075 U701.14@11.6,53.075
  Bottom Layer w0.305: R716.2@4.208,45.2 R717.2@5.508,45.2 R718.2@6.808,45.2 6.808,45.108 6.9,45.2 v1(6.9,46.2) ; v1(10.3,53.5) C720.1@11,53.5 R715.1@11.9,53.5
NetC720_2: C720.2 R714.1 R715.2 U701.13 | length 4
  Top Layer w0.305: v1(10.3,52.5) 10.375,52.425 U701.13@11.6,52.425
  Bottom Layer w0.305: R714.1@9.6,51.7 9.6,51.8 v1(10.3,52.5) C720.2@11,52.5 R715.2@11.9,52.5
NetC721_1: C721.1 R708.2 R709.1 R710.2 R713.2 R714.2 U701.8 | length 14.4
  Top Layer w0.203: v1(10.7,46.7) 10.7,48.3 v1(10.2,48.8) 10.575,49.175 U701.8@11.6,49.175
  Bottom Layer w0.203: v1(10.2,48.8) C721.1@11,48.8 R709.1@11.9,48.8
  Bottom Layer w0.305: R713.2@8.2,43.6 R710.2@9.6,43.6 R708.2@10.9,43.6 11.8,44.5 11.8,45.633 10.733,46.7 v1(10.7,46.7) ; R714.2@9.6,50.7 9.6,49.4 v1(10.2,48.8)
NetC721_2: C721.2 R709.2 R711.1 U701.9 | length 4.9
  Top Layer w0.203: v1(10.225,49.825) U701.9@11.6,49.825 12.575,49.825 13.1,49.3 R711.1@13.2,49.3
  Bottom Layer w0.203: v1(10.225,49.825) 10.25,49.8 C721.2@11,49.8 R709.2@11.9,49.8
NetC722_2: C722.2 C723.2 L703.2 R720.1 U701.4 | length 11.3
  Top Layer w0.305: L703.2@13.3,54.3 L703.2@13.4,54.2
  Top Layer w0.406: U701.4@5.6,51.125 7.025,51.125 v1(7.1,51.2)
  Top Layer w0.508: v1(7.1,51.2) 7.1,51.9 9.6,54.4 L703.2@13.4,54.4 ; R720.1@13.2,53.4 L703.2@13.2,54.2
  Bottom Layer w0.508: C723.2@7.1,50.4 v1(7.1,51.2)
NetC726_2: C726.2 R700.2 R705.1 TP700.1 U700.1 | length 23.5
  Top Layer w0.203: v1(20.5,50) 20.6,49.9 U700.1@21.05,49.9
  Bottom Layer w0.203: R705.1@2.8,51.5 R700.2@3.7,51.5 TP700.1@3.7,52.9 4.9,54.1 9.076,54.1 12.7,54.1 13.1,53.7 19.5,53.7 20.5,52.7 v1(20.5,50)
NetC728_2: C728.2 D700.1 L701.1 X700.2 | length 12.8
  Top Layer w0.203: L701.1@6.5,15 v1(7.9,15)
  Bottom Layer w0.203: v1(7.9,15) 11.4,15 11.7,15.3 C728.2@14.1,15.3 ; D700.1@14.1,16.351 14.295,16.546 D700.1@14.376,16.546
  Bottom Layer w0.305: X700.2@13.89,11.7 13.89,13.89 14.1,14.1 C728.2@14.1,15.3 D700.1@14.1,16.351
NetD400_16: D400.16 TP408.1 | length 2.1
  Bottom Layer w0.203: TP408.1@65.1,29.9 65.65,29.35 D400.16@65.65,28.055
NetD400_17: D400.17 TP409.1 | length 2.1
  Bottom Layer w0.203: D400.17@66.15,28.055 66.15,29.25 TP409.1@66.8,29.9
NetL403_1: L403.1 U404.8 | length 5.5
  Top Layer w0.305: 20.9,31.1 21,31.2 22.2,31.2 ; 22.1,31.3 22.2,31.2 ; 22.664,31.2 22.2,31.2 ; U404.8@24.55,31.35 24.55,31.3 22.3,31.3 22.2,31.2
  Top Layer w0.635: L403.1@20.9,30 20.9,31.1
NetL704_2: L704.2 R708.1 R710.1 R713.1 R728.1 | length 45.9
  Top Layer w0.305: v1(3.9,12.4) 4.6,12.4 L704.2@4.9,12.1
  Inner_GND w0.305: v1(2.4,44.3) 2.4,42.3 1.4,41.3 1.4,14.9 v1(3.9,12.4)
  Bottom Layer w0.305: v1(2.4,44.3) 3.3,45.2 3.3,45.8 3.7,46.2 4.1,46.2 R728.1@4.2,46.3 4.2,46.4 4.7,46.9 7.5,46.9 8.2,46.2 R713.1@8.2,45.1 ; R713.1@8.2,45.2 R710.1@9.6,45.2 R708.1@10.9,45.2
NetL705_2: L705.2 R728.2 U703.3 | length 38.9
  Top Layer w0.305: v1(3.1,43.7) 3.1,45.32 U703.3@4.55,46.77 ; v1(3.9,13.5) L705.2@4.9,13.5 L705.2@5,13.5 ; U703.3@4.6,46.77 5.014,46.356 6.044,46.356 v1(6.1,46.3)
  Inner_GND w0.305: v1(3.1,43.7) 3.1,42.2 1.9,41 1.9,15.5 v1(3.9,13.5)
  Bottom Layer w0.305: R728.2@5.2,46.3 6,46.3 v1@6.1,46.2
NetR1_2: R1.2 R26.2 U1.B6 | length 21.1
  Top Layer w0.152: v2(33.9,69.3) U1.B6@34.25,68.95 ; v2(35.4,58.9) 35.523,58.9 36.623,57.8 42.1,57.8 42.6,57.3 R26.2@42.6,56.7 R1.2@43.4,56.7
  Inner-1 w0.152: v2(33.9,69.3) 33.9,66.7 33.5,66.3 33.5,64.9 35.4,63 v2(35.4,58.9)
NetR2_2: R2.2 U1.G1 | length 3.9
  Top Layer w0.127: U1.G1@38.25,64.95 39.202,63.999 40.106,63.999 40.739,63.366 40.739,62.861 R2.2@40.9,62.7
NetR3_1: R3.1 U1.A8 | length 1.7
  Top Layer w0.254: R3.1@31.9,71 32.35,71 32.8,70.55 U1.A8@33.45,70.55
NetR10_2: R10.2 R11.1 V1.1 | length 3.1
  Top Layer w0.203: R11.1@40.9,54.9 41.7,54.9 ; R10.2@41.7,55.7 41.75,55.65 41.75,54.65 v1(41.8,54.6)
  Bottom Layer w0.305: V1.1@41.7,55.35 42,55.35 41.8,55.15 v1(41.8,54.6)
NetR18_1: R18.1 U1.D6 | length 8.6
  Top Layer w0.127: v2(32.2,68.4) 32.35,68.55 35.45,68.55 U1.D6@35.85,68.95
  Inner-1 w0.127: v1(28.3,68.4) v2(32.2,68.4)
  Bottom Layer w0.127: R18.1@28.3,67.6 v1(28.3,68.4)
NetR20_1: R20.1 U1.K1 | length 3.2
  Top Layer w0.127: U1.K1@40.65,64.95 40.65,64.65 42.3,63 R20.1@42.3,62.4
NetR200_1: R200.1 U1.N10 | length 13.9
  Top Layer w0.127: U1.N10@43.05,72.15 43.45,71.75 v1@44.5,71.75
  Top Layer w0.152: v1(46.45,61.1) R200.1@47.25,61.1
  Bottom Layer w0.152: v1(44.5,71.85) 44.5,70.406 46.799,68.108 46.799,65.149 46.45,64.8 46.45,61.45
NetR201_1: R201.1 U1.J10 | length 22.1
  Top Layer w0.127: U1.J10@39.85,72.15 40.2,72.5 v2(40.25,72.5)
  Top Layer w0.152: v1(46.45,60.275) R201.1@47.25,60.275
  Inner-1 w0.127: v2(40.25,72.5) 41.5,72.5 42,73 43.675,73 43.9,73.225 v1(45.35,73.225)
  Bottom Layer w0.152: v1(45.35,73.225) 44.9,73.225 43.95,72.275 43.95,70.55 46.511,67.989 46.511,65.411 45.9,64.8 45.9,60.825 v1(46.45,60.275)
NetR205_1: R205.1 U201.A8 | length 3.1
  Top Layer w0.127: R205.1@49.4,67.175 50.075,67.175 50.799,67.899 51.601,67.899 U201.A8@52,67.5
NetR205_2: R205.2 U201.B9 | length 2
  Top Layer w0.127: R205.2@49.4,67.725 50.225,67.725 50.8,68.3 U201.B9@51.2,68.3
NetR205_3: R205.3 U201.B8 | length 3
  Top Layer w0.127: R205.3@49.4,68.225 50.227,68.225 50.7,68.699 51.601,68.699 U201.B8@52,68.3
NetR205_4: R205.4 U201.C9 | length 1.9
  Top Layer w0.127: R205.4@49.4,68.775 50.275,68.775 50.6,69.1 U201.C9@51.2,69.1
NetR206_2: R206.2 R218.1 TP200.1 | length 4.2
  Top Layer w0.127: R218.1@47,77.9 R206.2@48,77.9 48,79.275 v1(47.6,79.675)
  Bottom Layer w0.127: TP200.1@47.6,78.4 v1(47.6,79.675)
NetR207_1: R207.1 U201.C8 | length 2.8
  Top Layer w0.127: R207.1@49.4,69.5 R207.1@49.4,69.5 51.601,69.499 U201.C8@52,69.1
NetR207_2: R207.2 U201.D9 | length 1.9
  Top Layer w0.127: R207.2@49.4,70.05 49.85,70.05 50,69.9 U201.D9@51.2,69.9
NetR207_3: R207.3 U201.D8 | length 2.9
  Top Layer w0.127: R207.3@49.4,70.55 49.85,70.55 50.1,70.3 51.6,70.3 U201.D8@52,69.9
NetR207_4: R207.4 U201.E9 | length 2
  Top Layer w0.127: R207.4@49.4,71.1 49.9,71.1 50.3,70.7 U201.E9@51.2,70.7
NetR212_1: R212.1 U201.E1 | length 7.9
  Top Layer w0.127: U201.E1@57.6,70.7 57.973,70.7 59.023,69.65 59.023,64.823 58.45,64.25 R212.1@58.05,64.25
NetR212_2: R212.2 U201.D2 | length 7.6
  Top Layer w0.127: U201.D2@56.8,69.9 56.8,70 56.811,69.989 56.889,69.989 57.199,70.299 57.765,70.299 58.761,69.303 58.761,65.161 58.4,64.8 R212.2@58.05,64.8
NetR212_3: R212.3 U201.D1 | length 5.4
  Top Layer w0.127: U201.D1@57.6,69.9 58.499,69.002 58.499,65.399 58.4,65.3 R212.3@58.05,65.3
NetR212_4: R212.4 U201.C1 | length 3.6
  Top Layer w0.127: U201.C1@57.6,69.1 58.15,68.55 58.15,65.85 R212.4@58.05,65.85
NetR213_1: R213.1 U201.B2 | length 6.6
  Top Layer w0.127: R213.1@54.45,64.25 54.8,64.25 55.441,64.891 55.441,65.448 56.269,66.275 56.775,66.275 v2(56.9,66.4) ; U201.B2@56.8,68.3 56.825,68.3 v2(57.2,68.675)
  Inner-1 w0.127: v2(56.9,66.4) 56.9,68.375 v2(57.2,68.675)
NetR213_2: R213.2 U201.B1 | length 5.2
  Top Layer w0.127: R213.2@54.45,64.8 54.771,64.8 55.179,65.209 55.179,65.556 56.16,66.537 56.508,66.537 57.2,67.229 57.2,67.9 U201.B1@57.6,68.3
NetR213_3: R213.3 U201.A2 | length 3.6
  Top Layer w0.127: R213.3@54.45,65.3 54.775,65.3 54.917,65.442 54.917,65.665 56.052,66.8 56.4,66.8 56.8,67.2 U201.A2@56.8,67.5
NetR213_4: R213.4 U201.C2 | length 4.5
  Top Layer w0.127: R213.4@54.45,65.85 54.6,66 54.8,66 55.862,67.062 56.126,67.062 56.4,67.336 56.4,68.7 U201.C2@56.8,69.1
NetR214_2: R214.2 U1.M4 | length 4.1
  Top Layer w0.127: v2(45.3,67.3) 45.475,67.475 45.475,67.8 R214.2@45.55,67.875
  Top Layer w0.152: U1.M4@42.25,67.35 v2(42.65,67.75)
  Inner-1 w0.127: v2(42.65,67.75) 43.089,67.311 45.289,67.311 v2(45.3,67.3)
NetR215_1: R215.1 U1.D10 | length 9
  Top Layer w0.127: v2(35.45,71.75) U1.D10@35.85,72.15
  Inner-1 w0.152: v1(28.7,71.2) 29.1,71.6 31.5,71.6 32.3,70.8 34.5,70.8 v2(35.45,71.75)
  Bottom Layer w0.152: R215.1@28.624,70.404 28.7,70.48 v1(28.7,71.2)
NetR216_1: R216.1 U1.D9 | length 6.2
  Top Layer w0.152: U1.D9@35.85,71.35 v2(36.25,71.75)
  Inner-1 w0.152: v1(32.7,69.9) 33.3,70.5 35,70.5 v2(36.25,71.75)
  Bottom Layer w0.152: R216.1@31.8,70.6 32.2,70.6 32.614,70.186 32.614,69.986 v1(32.7,69.9)
NetR217_1: R217.1 U1.F4 | length 5.2
  Top Layer w0.127: U1.F4@37.45,67.35 v2(37.8,67)
  Inner-1 w0.127: v1(37,63.5) 37.8,64.3 v2(37.8,67)
  Bottom Layer w0.127: R217.1@36.104,63.476 36.128,63.5 v1(37,63.5)
NetR300_2: R300.2 U333.49 | length 1.9
  Top Layer w0.152: U333.49@65.45,45.2 65.45,44.75 65.611,44.589 65.611,44.011 65.4,43.8 65.4,43.6 R300.2@65.5,43.5
NetR302_2: R302.2 U333.19 | length 8.4
  Top Layer w0.152: R302.2@60.7,57 60.9,56.8 61.1,56.8 62.703,55.197 65.938,55.197 66.95,54.185 U333.19@66.95,53.2
NetR303_2: R303.2 U333.20 | length 7.6
  Top Layer w0.152: R303.2@60.7,56.2 61.294,56.2 62.584,54.91 65.818,54.91 66.45,54.278 U333.20@66.45,53.2
NetR304_2: R304.2 U333.21 | length 6.8
  Top Layer w0.152: R304.2@60.7,55.4 v2(61.3,55.4) ; U333.21@65.95,53.2 65.95,53.65 66,53.7 v2(66,54.2)
  Inner-1 w0.152: v2(61.3,55.4) 61.3,55.375 62.1,54.575 65.625,54.575 v2(66,54.2)
NetR320_1: R320.1 U333.9 | length 2.6
  Top Layer w0.152: U333.9@69.7,49.95 72.05,49.95 R320.1@72.1,49.9 R320.1@71.95,49.75
NetR321_2: R321.2 U333.8 | length 2.9
  Top Layer w0.152: U333.8@69.7,49.45 70.15,49.45 70.3,49.6 71.1,49.6 71.6,49.1 R321.2@72.1,49.1 R321.2@71.95,49.25
NetR322_1: R322.1 U333.10 | length 2.5
  Top Layer w0.152: U333.10@69.7,50.45 69.731,50.419 71.319,50.419 71.6,50.7 R322.1@72.1,50.7
NetR323_2: R323.2 U333.42 | length 2.7
  Top Layer w0.152: R323.2@59.2,46.2 60.1,46.2 60.431,45.869 61.169,45.869 61.25,45.95 U333.42@61.7,45.95
NetR324_2: R324.2 U333.39 | length 2.8
  Top Layer w0.152: R324.2@59.2,47.8 59.7,47.8 59.875,47.625
  Top Layer w0.16: 59.875,47.625 60.2,47.3 60.9,47.3 61.05,47.45 U333.39@61.7,47.45
NetR325_2: R325.2 U333.29 | length 1.7
  Top Layer w0.152: v1(61,52.9) 61.45,52.45 U333.29@61.7,52.45
  Bottom Layer w0.152: v1(61,52.9) 61.374,52.526 R325.2@61.6,52.3
NetR326_2: R326.2 U333.15 | length 2.8
  Top Layer w0.152: U333.15@68.95,53.2 68.961,53.211 71.589,53.211 R326.2@71.7,53.1
NetR329_1: R329.1 U333.30 | length 2.4
  Top Layer w0.152: R329.1@59.5,52.5 60.6,52.5 61.15,51.95 U333.30@61.7,51.95
NetR330_1: R330.1 U333.17 | length 4.6
  Top Layer w0.152: U333.17@67.95,53.2 67.95,53.65 68.5,54.2 70.8,54.2 71.171,54.571 71.571,54.571 R330.1@71.7,54.7
NetR332_2: R332.2 U333.40 | length 2.3
  Top Layer w0.152: R332.2@59.2,47 R332.2@59.25,46.95 ; R332.2@59.45,46.95 U333.40@61.7,46.95
NetR333_2: R333.2 U333.16 | length 3.8
  Top Layer w0.152: U333.16@68.45,53.2 68.45,53.65 68.7,53.9 R333.2@71.7,53.9
NetR401_2: R401.2 U400.2 | length 1.8
  Top Layer w0.203: U400.2@24.5,24.1 25.2,24.1 R401.2@26,23.3
NetR402_1: R402.1 TP403.1 U400.13 | length 3.2
  Top Layer w0.203: R402.1@18.3,24.5 19.107,24.5 19.335,24.728 19.878,24.728 U400.13@19.9,24.75
  Bottom Layer w0.203: TP403.1@17.5,24.4 17.55,24.4 17.65,24.5 v1(19,24.5)
NetR403_2: R403.2 U400.8 | length 6.6
  Top Layer w0.203: U400.8@22.2,27.05 v1(22.2,28.3)
  Bottom Layer w0.203: v1(22.2,28.3) 22.2,26.6 24.4,24.4 R403.2@24.9,24.4
NetR405_2: R405.2 U400.3 | length 1.5
  Top Layer w0.203: U400.3@24.5,24.75 25.95,24.75 R405.2@26,24.8
NetR406_2: R406.2 U400.6 | length 3.4
  Top Layer w0.203: U400.6@23.5,27.05 23.5,27.6 23.6,27.7 v1(23.6,28.3)
  Bottom Layer w0.203: v1(23.6,28.3) 23.6,27.3 R406.2@24.4,26.5
NetR407_2: R407.2 U400.10 | length 1.1
  Top Layer w0.203: R407.2@20.7,28.1 20.7,27.6 20.9,27.4 U400.10@20.9,27.05
NetR408_1: R408.1 U400.7 | length 4.8
  Top Layer w0.203: U400.7@22.85,27.05 v1(22.85,27.9)
  Bottom Layer w0.203: v1(22.85,27.9) 22.85,26.55 24.1,25.3 R408.1@24.9,25.3
NetR409_1: R409.1 U400.9 | length 1.8
  Top Layer w0.203: U400.9@21.55,27.05 v1(21.55,27.9)
  Bottom Layer w0.203: v1@21.5,27.85 v1(21.55,27.9)
  Bottom Layer w0.305: R409.1@20.6,27.9 v1@21.5,27.9
NetR410_2: R410.2 U402.1 | length 1.5
  Top Layer w0.203: R410.2@24.9,35.2 24.9,36.635 U402.1@24.965,36.7
NetR411_2: R411.2 U403.1 | length 2
  Top Layer w0.203: R411.2@28.3,35 28.265,35.035 U403.1@28.265,36.7 U403.1@28.5,36.465
NetR412_1: R412.1 R416.2 U404.2 | length 8.1
  Top Layer w0.152: R412.1@17.7,28.7 R416.2@18.7,28.7 18.9,28.9 24.8,28.9 25.05,29.15 U404.2@25.05,29.25 ; U404.2@25.05,29.65 U404.2@25.05,29.25 ; U404.2@25.1,29.3 U404.2@25.05,29.25
NetR414_2: R414.2 R417.1 U404.4 | length 2.1
  Top Layer w0.305: U404.4@26.05,29.65 26.2,29.8 27,29.8 R417.1@27.1,29.9 R414.2@27.1,30.8
NetR419_2: R419.2 U405.1 | length 1.8
  Bottom Layer w0.203: U405.1@25.635,36.2 25.635,34.465 R419.2@25.7,34.4
NetR420_1: R420.1 U407.1 | length 3.4
  Top Layer w0.203: v1(26.6,44.6) R420.1@26.6,45.3
  Bottom Layer w0.203: v1(26.6,44.6) 26.6,43.3 27.1,42.8 U407.1@27.765,42.8
NetR421_1: R421.1 U408.10 | length 2.4
  Top Layer w0.203: R421.1@39.3,40.8 40,40.8 v1@40.2,40.6
  Bottom Layer w0.203: v1(40.145,40.667) 40.72,41.242 U408.10@40.72,41.8
NetR422_1: R422.1 U408.7 | length 1.4
  Bottom Layer w0.152: U408.7@40.775,47.067 40.775,48.175 R422.1@41,48.4
NetR427_2: R427.2 U406.48 | length 3
  Top Layer w0.254: v1(32.9,37.1) 33.65,36.35 U406.48@34.7,36.35
  Bottom Layer w0.254: v1(32.9,37.1) R427.2@33.8,37.1
NetR428_2: R428.2 U406.49 | length 2.8
  Top Layer w0.254: v1(32.9,36.2) 33.25,35.85 U406.49@34.7,35.85
  Bottom Layer w0.254: v1(32.9,36.2) R428.2@33.8,36.2
NetR429_2: R429.2 U406.50 | length 2.7
  Top Layer w0.254: v1(32.9,35.3) 32.95,35.35 U406.50@34.7,35.35
  Bottom Layer w0.254: v1(32.9,35.3) R429.2@33.8,35.3
NetR430_2: R430.2 U406.51 | length 2.9
  Top Layer w0.254: v1(32.9,34.4) 33.35,34.85 U406.51@34.7,34.85
  Bottom Layer w0.254: v1(32.9,34.4) R430.2@33.8,34.4
NetR600_2: R600.2 U600.5 | length 2
  Top Layer w0.152: U600.5@47.3,46.297 47.3,45.3 47.311,45.289 v1(47.326,45.289)
  Bottom Layer w0.152: R600.2@47.3,46.3 47.326,46.274 v1(47.326,45.289)
NetR601_2: R601.2 R602.2 R603.1 | length 1.9
  Bottom Layer w0.203: R603.1@49.2,45.4 R602.2@49.2,46.3 R601.2@50.2,46.3
NetR602_1: R602.1 U600.6 | length 3.3
  Top Layer w0.152: U600.6@46.348,46.297 46.172,46.472 46.9,47.2 v1(47.8,47.2)
  Bottom Layer w0.152: v1(47.8,47.2) 47.775,47.2 48.2,46.775 R602.1@48.2,46.3
NetR604_1: R604.1 U601.5 | length 1.2
  Top Layer w0.203: R604.1@26.8,49 U601.5@28.003,49
NetR605_2: R605.2 R606.2 R607.1 | length 1.8
  Bottom Layer w0.203: R606.2@28,49 R607.1@28.9,49 R605.2@28.9,49.9
NetR606_1: R606.1 U601.6 | length 1.7
  Top Layer w0.203: v1(28,47.2) 28,47.956 27.956,48 28,48.044 U601.6@28.003,48.047
  Bottom Layer w0.203: v1(28,47.2) R606.1@28,48
NetR701_1: R701.1 R704.1 U701.1 | length 2.6
  Top Layer w0.203: R701.1@3.2,53.5 R704.1@4.1,53.5 4.525,53.075 U701.1@5.6,53.075
NetR702_1: R702.1 U700.7 | length 1.8
  Top Layer w0.152: U700.7@24.3,50.65 24.75,50.65 25.3,50.1 25.7,50.1 R702.1@25.8,50
NetR704_2: R704.2 R724.1 U701.2 | length 4.8
  Top Layer w0.203: R704.2@4.125,52.425 U701.2@5.6,52.425 6.425,52.425 6.7,52.7 6.7,53.3 6.5,53.5 v1(6.7,53.5)
  Bottom Layer w0.305: R724.1@5.7,53.5 v1(6.7,53.5)
NetR716_1: R716.1 R717.1 R718.1 U703.4 | length 5.4
  Top Layer w0.305: v1(4.2,42.6) 4.2,43.83 U703.4@4.6,44.23
  Bottom Layer w0.305: R716.1@4.2,43.592 v1(4.2,42.6) v1@4.208,42.608 ; R716.1@4.208,43.6 R717.1@5.508,43.6 R718.1@6.808,43.6
NetR719_1: R719.1 V700.3 | length 2.4
  Bottom Layer w0.305: R719.1@17.1,44.5 19.402,44.5 19.5,44.402 V700.3@19.5,44.4
NetR719_2: R719.2 U703.2 | length 5
  Top Layer w0.305: v1(12.9,45.6) 12.9,46.7 12.985,46.785 U703.2@13,46.77
  Bottom Layer w0.305: v1@12.9,45.52 v1(12.9,45.6) 14,44.5 16,44.5 R719.2@16.1,44.6
NetR721_2: R721.2 V700.1 | length 1.2
  Bottom Layer w0.305: V700.1@20.4,42.7 20.45,42.65 21.537,42.65 R721.2@21.587,42.7
NetT300_13: T300.13 X300.8 | length 7.8
  Top Layer w0.203: T300.13@47.615,22.96 47.615,21.285 48.335,20.565 48.4,20.63 v1(48.4,20.5)
  Bottom Layer w0.203: X300.8@47.14,16.15 47.14,17.44 48.4,18.7 v1(48.4,20.5)
NetT300_14: T300.14 X300.7 | length 10.9
  Top Layer w0.203: v1(48.6,21.3) 48.885,21.585 T300.14@48.885,22.96
  Bottom Layer w0.203: X300.7@45.87,13.61 45.9,13.64 45.9,16.9 47.8,18.8 47.8,21 48.1,21.3 v1(48.6,21.3)
NetT300_16: T300.16 X300.5 | length 16.2
  Top Layer w0.203: v1(43.4,18.3) 44.8,19.7 50.8,19.7 51.425,20.325 T300.16@51.425,22.96
  Bottom Layer w0.203: X300.5@43.33,13.61 43.4,13.68 v1(43.4,18.3)
NetT300_17: T300.17 X300.4 | length 14.8
  Top Layer w0.203: X300.4@42.06,16.15 45.11,19.2 ; 45.1,19.2 45.11,19.2 ; T300.17@52.695,22.96 52.695,21.6 52,20.905 52,20 51.2,19.2 45.11,19.2
NetT301_13: T301.13 X301.8 | length 11.9
  Top Layer w0.22: T301.13@67.465,22.96 67.465,21.535 69.7,19.3 v1(70.9,19.3) ; X301.8@71.14,16.15 71.14,16.64 73.2,18.7 v1(73.2,18.9)
  Bottom Layer w0.22: v1(70.9,19.3) 72.8,19.3 v1(73.2,18.9)
NetT301_14: T301.14 X301.7 | length 15.3
  Top Layer w0.22: T301.14@68.735,22.96 68.735,21.165 69.9,20 v1(71.4,20) ; X301.7@69.87,13.61 70.56,14.3 70.9,14.3 72.3,15.7 72.3,17 v1(74.1,18.8)
  Bottom Layer w0.22: v1(71.4,20) 72.9,20 v1(74.1,18.8)
NetT301_16: T301.16 X301.5 | length 16.6
  Top Layer w0.22: X301.5@67.33,13.61 66.04,14.9 65.6,14.9 65,15.5 65,16.8 65.6,17.4 66.7,17.4 67.7,18.4 71.4,18.4 72,19 72,20.675 71.275,21.4 T301.16@71.275,22.96
NetT301_17: T301.17 X301.4 | length 11.7
  Top Layer w0.22: X301.4@66,16.2 66.3,16.2 68,17.9 71.5,17.9 72.4,18.8 72.4,22.815 T301.17@72.545,22.96
NetTP302_1: TP302.1 U333.13 | length 1.8
  Top Layer w0.152: U333.13@69.7,51.95 70.45,51.95 70.6,52.1 TP302.1@71.4,52.1
NetTP303_1: TP303.1 U333.12 | length 4.3
  Top Layer w0.152: U333.12@69.7,51.45 70.25,51.45 70.3,51.5 70.9,51.5 ; 70.9,51.481 70.919,51.481 71.1,51.3 73.3,51.3 TP303.1@73.7,51.7
NetTP401_1: TP401.1 U400.19 | length 2.2
  Top Layer w0.203: U400.19@22.85,22.45 22.85,21.95 23.3,21.5 24.1,21.5 TP401.1@24.3,21.3
NetTP404_1: TP404.1 U400.16 | length 3.8
  Top Layer w0.203: v1(19,23) 19.1,22.9 20,22.9 20.2,22.9 20.5,22.6 20.9,22.6 U400.16@20.9,22.45
  Bottom Layer w0.203: TP404.1@17.5,22.9 17.6,23 v1(19,23)
NetU408_5: U408.5 U409.2 | length 2.6
  Top Layer w0.152: v1@37.8,48.2 37.9,48.1 38.8,48.1 U409.2@38.9,48
  Bottom Layer w0.152: v1(37.745,48.267) 37.945,48.267 38.18,48.032 U408.5@38.18,47.134
NetU701_6: U701.6 U701.7 | length 2.3
  Top Layer w0.203: U701.7@5.6,49.175 6.375,49.175 6.5,49.3 6.5,49.7 6.4,49.8 U701.6@5.6,49.8
NRESET: C3.2 TP100.1 U1.C7 U2.2 X2.10 | length 24.9
  Top Layer w0.152: U2.2@27.6,60.5 27.6,60.2 28.3,59.5 29.9,59.5 31.2,58.2 v1(32.1,58.2) ; U2.2@27.6,60.6 28,60.6 28.3,60.9 C3.2@28.3,61.7 ; v2(34.7,70.1) U1.C7@35.05,69.75
  Inner-1 w0.152: v1(32.1,58.2) 32.039,58.261 32.039,64.239 33.2,65.4 33.2,66.5 33.5,66.8 33.5,69.428 34.172,70.1 v2(34.7,70.1)
  Bottom Layer w0.152: v1(32.1,58.2) 32.7,57.6 TP100.1@32.8,57.6 X2.10@32.8,55.69 ; X2.10@32.466,56.5 32.76,56.206 X2.10@32.76,55.65
NWE: U1.P3 U201.F9 | length 13.4
  Top Layer w0.127: U1.P3@43.85,66.55 44.35,66.55 v2(44.4,66.5) ; v2(47.175,66.875) v2(47.175,72.175) ; v2(50.6,71.5) U201.F9@51.2,71.5
  Inner-1 w0.127: v2(44.4,66.5) 45.075,66.5 45.375,66.2 46.5,66.2 v2(47.175,66.875) ; v2(47.175,72.175) 49.925,72.175 v2(50.6,71.5)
